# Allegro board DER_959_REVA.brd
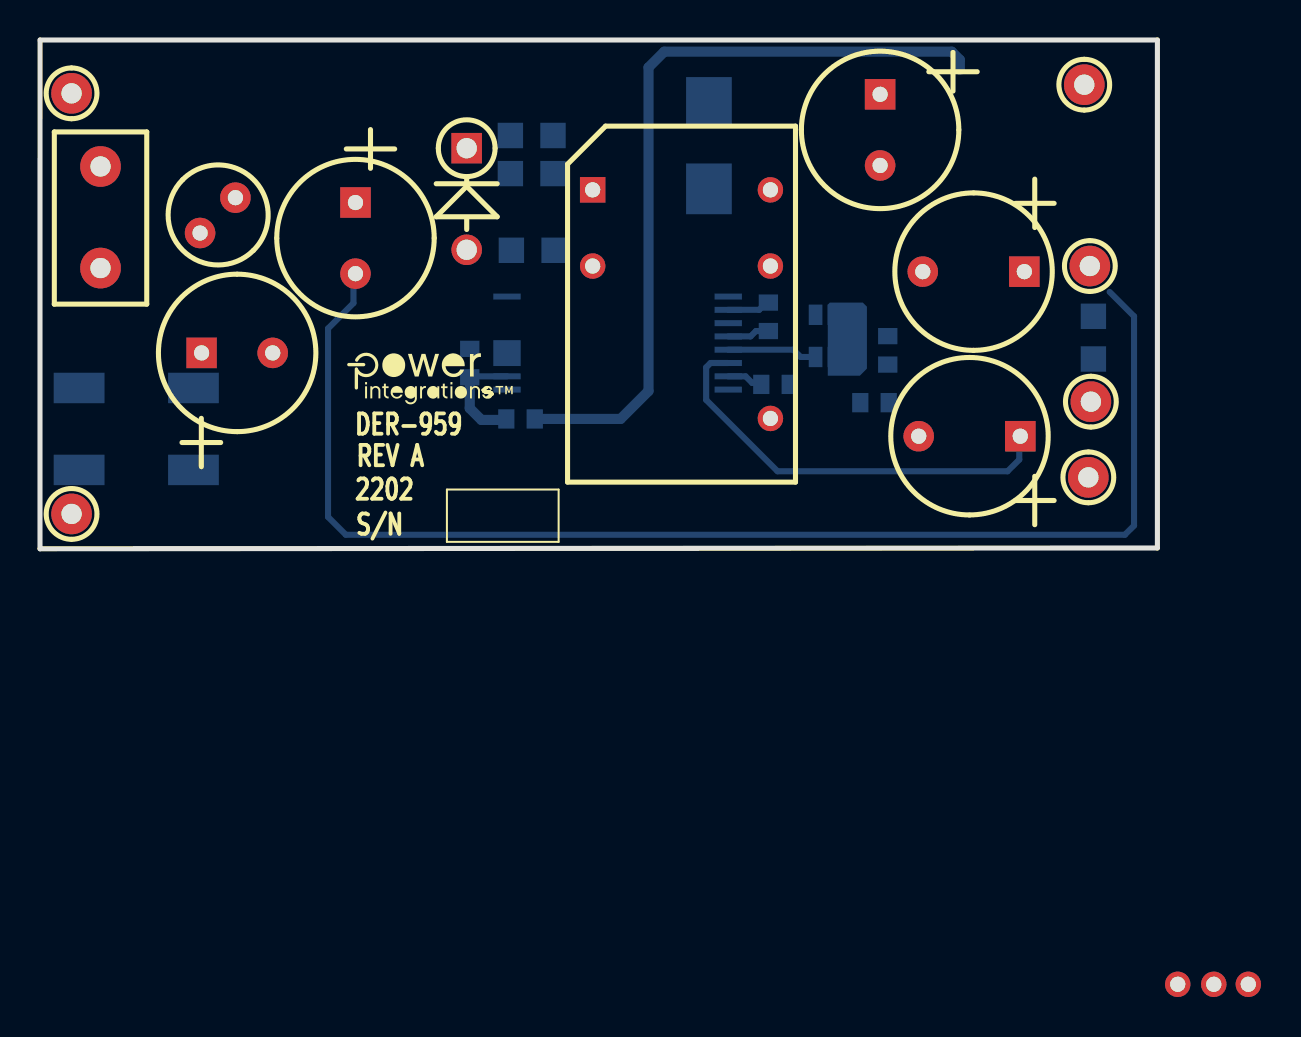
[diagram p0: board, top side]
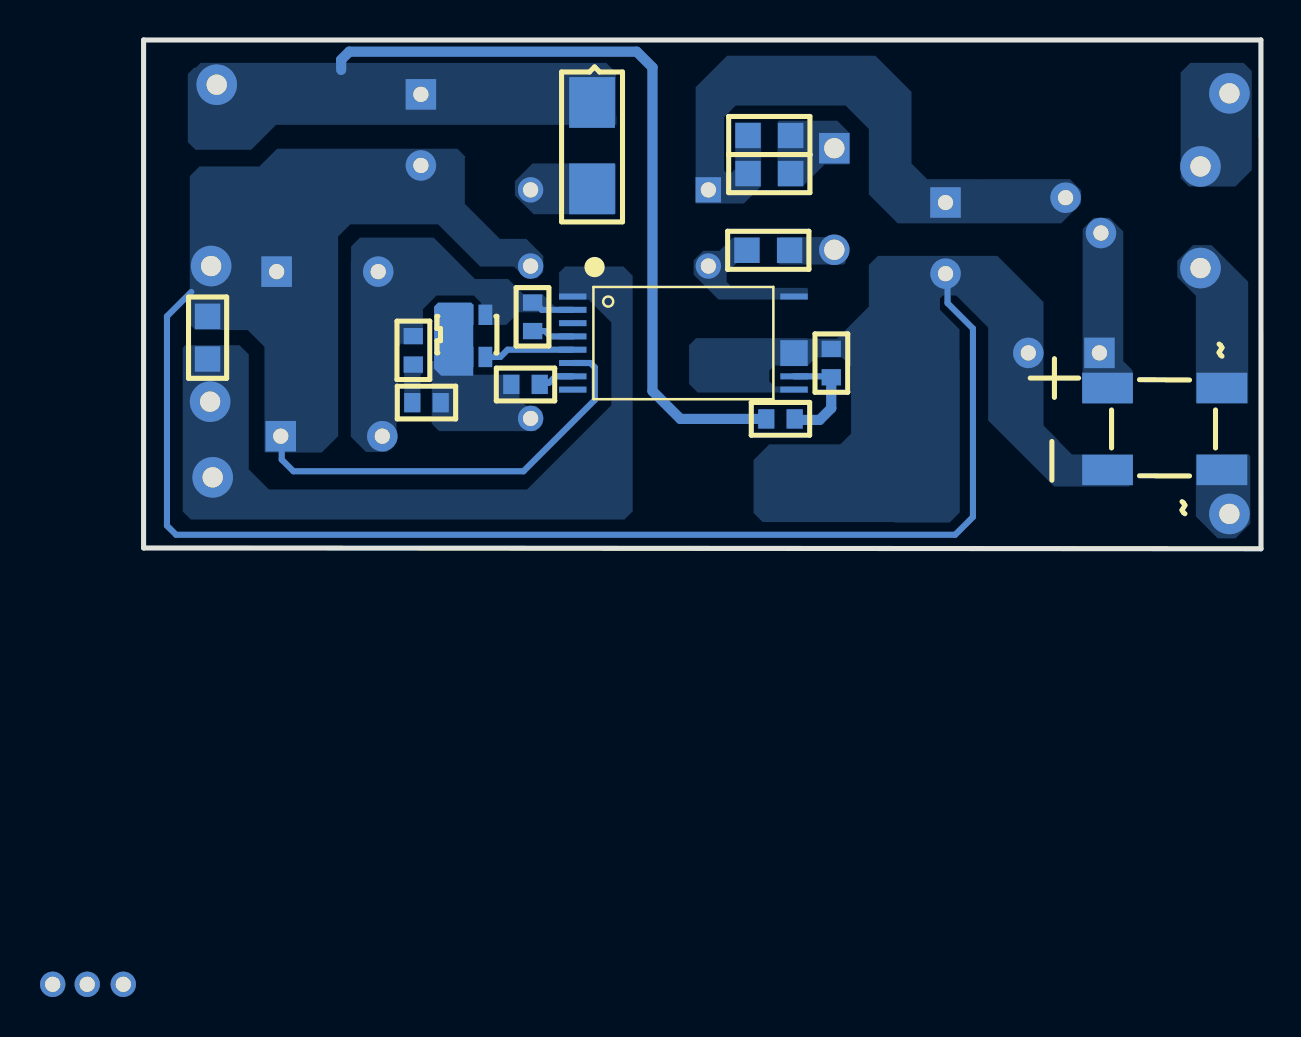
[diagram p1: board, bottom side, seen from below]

Outline 55.89 x 25.44 mm; copper layers: TOP, BOTTOM. Coordinates in mm from the lower left corner of the outline.
Outline path: 0,0 55.89,0.04 55.89,25.44 0.01,25.44 0,0

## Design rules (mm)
constraint set DEFAULT: min track width 0.508

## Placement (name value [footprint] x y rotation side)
BR1  ABS210-13  [PISMD_SOPA-4]  7.68 8.04 90 bottom
C1  4.7 uF  [PIPOLCAPCLYD320LS140030]  8.08 9.79 0 top
C2  4.7 uF  [PIPOLCAPCLYD320LS140030]  15.78 17.31 270 top
C3  220 pF  [PISMC0805]  25.66 18.76 180 bottom
C4  0.47 uF  [PISMC0603]  21.49 8.58 90 bottom
C5  1000 pF  [PISMC0603]  42.4 9.21 90 bottom
C6  2.2 uF  [PISMC0603]  36.43 12.31 270 bottom
C7  1000 uF  [PIPOLCAPCLYD320LS140030]  42.02 22.72 270 top
C8  820 uF  [PI_POLCAP_D320LS200D030]  46.69 13.86 180 top
C9  820 uF  [PI_POLCAP_D320LS200D030]  46.49 5.63 180 top
C10  2.2 uF  [PISMC0805]  52.68 11.62 270 bottom
D1  1N4007  [PIDV200X110X040DO41]  21.34 20.03 270 top
D2  VSSA210-M3/5AT  [PISMDO214AC12]  33.46 22.32 270 bottom
F1  1 A  [PI_RST_MICROFUSE]  3.03 14.04 90 top
L1  330 uH  [PICHOKETOKINVD216H413LS098D030]  8.01 15.79 45 top
LINE  BLK  [PITPKEYSTONE100X100]  1.58 22.77 0 top
NEUTRAL  WHT  [PITPKEYSTONE100X100]  1.58 1.74 0 top
NOREF  -  []  0.01 25.44 0 top
NOREF#2  -  []  0.01 0.04 90 top
NOREF#3  -  []  -140.04 52.4 0 top
NOREF#4  -  []  -217.85 -146.62 0 top
NOREF#5  -  []  14.81 9.69 0 top
Q1  AO6420  [PISMSOT236_SHORT1256]  40.67 9.59 180 bottom
R1  470 k  [PISMR0805]  25.66 20.67 180 bottom
R2  20  [PISMR0805]  23.58 14.93 0 bottom
R3  20  [PISMR0603]  41.03 7.31 0 bottom
R4  47  [PISMR0603]  37.5 8.22 180 bottom
R5  7.5 k  [PISMR0603]  23.32 6.49 0 bottom
T1  EF16  [PIBOBBINEF16V8P]  27.64 17.95 0 top
TP1  YEL  [PITPKEYSTONE100X100]  52.23 23.21 0 top
TP2  RED  [PITPKEYSTONE100X100]  52.51 14.14 0 top
TP3  BLK  [PITPKEYSTONE100X100]  52.56 7.36 0 top
TP4  BLK  [PITPKEYSTONE100X100]  52.43 3.57 0 top
U1  INN3072M  [PI_SM_MINSOP16A_1]  34.42 12.61 270 bottom

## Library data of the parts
BR1 = DIODE BRIDGE_+~~-: alternate symbols: (pismd_SOPA-4a,pi_sm_soic4_slot)
C1 C2 = CAP POL: alternate symbols: (pipolcapclyd320ls140030h)
C3-C5 C10 = CAP NP
C6 = CAP NP: alternate symbols: (pismc0603_1)
C7 = CAP POL: alternate symbols: (pipolcapclyd320ls140d30h750)
C8 C9 = CAP POL
D1 = DIODE: alternate symbols: (pidax475x125040do41,pidv200x110x040do41wbead,pidax390x125040do41)
D2 = DIODE SCHOTTKY
F1 = FUSE: alternate symbols: (pirstmicrofusehoz)
L1 = INDUCTOR
LINE TP1 TP3 TP4 = TESTPOINT: alternate symbols: (TP_TH_CR2_D1_1)
NEUTRAL TP2 = TESTPOINT
Q1 = FET_N_DGS
R1-R3 R5 = R
R4 = R: alternate symbols: (pismr0603_1)
T1 = BEF16/8PINS/GENERIC
U1 = Inno3TNMinSOP16_2

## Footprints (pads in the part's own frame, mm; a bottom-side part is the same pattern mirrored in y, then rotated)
PI_POLCAP_D320LS200D030
  rect 1.524x1.524 hole 0.762: 1(-2.54,0)
  round 1.524 hole 0.762: 2(2.54,0)
PI_RST_MICROFUSE
  round 2.032 hole 1.016: 1(0,0) 2(5.08,0)
PI_SM_MINSOP16A_1
  rect 0.3x1.369 smd: 1(0,0) 2(0.665,0) 3(1.331,0) 4(1.994,0) 5(2.659,0) 6(3.325,0) 7(3.99,0) 8(4.656,0) 9(4.656,11.067) 10(3.99,11.067) 16(0,11.067)
  rect 1.293x1.369 smd: 11(2.83,11.067)
PIBOBBINEF16V8P
  rect 1.27x1.27 hole 0.762: 1(0,0)
  round 1.27 hole 0.762: 2(0,-3.81) 3(29.261,-39.726) 4(31.064,-39.726) 5(8.89,-11.43) 6(32.791,-39.726) 7(8.89,-3.81) 8(8.89,0)
PICHOKETOKINVD216H413LS098D030
  round 1.524 hole 0.762: 1(0,0) 2(2.499,0)
PIDV200X110X040DO41
  rect 1.524x1.524 hole 1.016: 1(0,0)
  round 1.524 hole 1.016: 2(5.08,0)
PIPOLCAPCLYD320LS140030
  rect 1.524x1.524 hole 0.762: 1(0,0)
  round 1.524 hole 0.762: 2(3.556,0)
PISMC0603
  rect 0.813x0.965 smd: 1(0,0) 2(1.422,0)
PISMC0805
  rect 1.27x1.27 smd: 1(0,0) 2(2.134,0)
PISMD_SOPA-4
  rect 1.524x2.54 smd: 1(0,0) 2(0,-5.72) 3(-4.1,-5.72) 4(-4.1,0)
PISMDO214AC12
  rect 2.54x2.286 smd: 1(0,0) 2(4.318,0)
PISMR0603
  rect 0.813x0.965 smd: 1(0,0) 2(1.422,0)
PISMR0805
  rect 1.27x1.27 smd: 1(0,0) 2(2.134,0)
PISMSOT236_SHORT1256
  rect 0.686x1.016 smd: (0,2.108) (0.94,0) (0.94,2.108) 1(0,0) 3(1.88,0) 4(1.88,2.108)
PITPKEYSTONE100X100
  round 2.032 hole 1.016: 1(0,0)

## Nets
+12V: C7.1 D2.1 R5.2 TP1.1
3: U1.3
8: U1.8
RTN: C10.2 TP3.1 TP4.1 U1.1
N12175216: F1.2 LINE.1
N12175256: BR1.1 C1.1 L1.1
N12175292: C2.1 C3.1 L1.2 R1.1 T1.1
N12175504: C3.2 D1.1 R1.2
N12175524: BR1.4 C1.2 C2.2 C4.2 C7.2 C8.1 C9.1 C10.1 T1.7 TP2.1 U1.6 U1.9 U1.11
N12175646: Q1.1 R3.1 R4.1 T1.5
N12175650: C5.1 R3.2
N12175654: C5.2 C6.1 C8.2 C9.2 Q1.4(S) U1.2
N12175712: D1.2 R2.1
N12175716: R2.2 T1.2 U1.16
N12175890: Q1.3 U1.5
N12175950: BR1.3 NEUTRAL.1
N12175954: C6.2 U1.4
N12176066: C4.1 R5.1 U1.10
N12179234: R4.2 U1.7
N12183686: D2.2 T1.8
N12199280: BR1.2 F1.1

Pads without a net: T1 3 4 6

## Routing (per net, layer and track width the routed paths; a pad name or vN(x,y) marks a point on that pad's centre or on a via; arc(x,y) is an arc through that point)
+12V: length 39
  BOTTOM w0.508: 46,23.94 46,24.45 45.6,24.86 31.22,24.86 30.43,24.07 30.43,7.89 29.04,6.49 R5.2
N12175524: length 87.2
  BOTTOM w0.305: C9.1 48.98,5.58 48.98,4.46 48.39,3.88 36.89,3.88 33.32,7.44 33.32,9.07 33.54,9.29 U1.6 ; 53.5,12.84 54.72,11.62 54.72,1.16 54.26,0.7 15.3,0.7 14.41,1.59 14.41,11.01 15.68,12.28 15.68,13.27 15.83,13.43 15.83,13.71 C2.2
N12175654: length 2.2
  BOTTOM w0.305: U1.2 35.97,11.95 36.33,12.31 C6.1
N12175716: length 0.2
  BOTTOM w0.508: 27.61,14.21 27.79,14.21
N12175890: length 4.5
  BOTTOM w0.305: Q1.3 38.04,9.59 37.68,9.95 U1.5
N12175954: length 2.1
  BOTTOM w0.305: U1.4 35.54,10.62 35.81,10.89 C6.2
N12176066: length 5.5
  BOTTOM w0.305: U1.10 21.54,8.62 C4.1
  BOTTOM w0.508: R5.1 23.27,6.44 22.08,6.44 21.49,7.03 C4.1
N12179234: length 1.8
  BOTTOM w0.305: U1.7 35.29,8.62 35.62,8.3 36,8.3 R4.2

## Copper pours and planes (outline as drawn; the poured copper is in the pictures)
+12V on BOTTOM: 32.26,23.82 32.26,21.68 32.24,21.66 32.24,21.17 32.26,21.2 49.26,21.2 50.5,19.95 53.29,19.95 53.68,20.34 53.68,23.74 53.36,24.06 53.27,24.06 53.03,24.3 32.75,24.3
RTN on BOTTOM: 53.8,10.18 53.93,10.05 53.93,1.87 53.52,1.46 31.83,1.46 31.42,1.87 31.42,13.66 31.88,14.11 34.8,14.11 35.11,13.81 35.11,12.56 35.01,12.46 33.63,12.46 32.49,11.32 32.49,7.18 36.71,2.96 49.61,2.96 50.63,3.98 50.63,9.72 51.08,10.18
N12175216 on BOTTOM: 1.29,18.11 0.46,18.94 0.46,23.89 0.87,24.3 3.54,24.3 4.02,23.82 4.02,18.53 3.6,18.11
N12175256 on BOTTOM: 8.92,15.99 8.92,7.25 8.91,7.24 6.43,7.24 6.43,8.93 6.89,9.39 6.89,15.86 7.57,16.55 8.36,16.55
N12175292 on BOTTOM: 19.26,24.65 26.7,24.65 28.28,23.08 28.28,17.26 25.86,17.26 25,18.13 25,21.3 26.29,21.3 26.29,18.99 26.5,18.79 26.73,18.79 26.85,18.91 26.85,21.58 26.27,22.16 20.78,22.16 19.61,21 19.61,17.72 18.17,16.27 9.99,16.27 9,17.26 9,17.92 9.56,18.48 14.13,18.48 14.15,18.46 14.18,18.48 16.69,18.48 17.48,19.27 17.48,22.85 19.26,24.63
N12175504 on BOTTOM: 24.11,21.4 24.19,21.33 24.19,18.15 24.16,18.13 22.92,18.13 21.82,19.22 20.6,19.22 20.58,19.24 20.58,20.79 21.19,21.4
N12175524 on BOTTOM: 40.19,20.01 49.2,20.01 50.09,19.12 53.09,19.12 53.57,18.63 53.57,11.22 53.29,10.94 50.68,10.94 49.84,10.1 49.84,4.84 49.81,4.82 46.97,4.82 46.16,5.63 46.16,15.61 45.55,16.22 41.15,16.22 39.04,14.11 37.37,14.11 36.78,13.53 36.2,13.53 35.9,13.83 35.9,14.65 36.75,15.5 38.07,15.5 39.82,17.25 39.82,19.56 39.78,19.6
N12175524 on BOTTOM: 13.19,14.65 19.16,14.65 19.61,14.19 19.61,12.11 21.21,10.51 22.69,10.51 22.71,10.53 28.25,10.53 28.61,10.18 28.61,8.24 28.17,7.81 22.66,7.81 22.66,8.09 22.69,8.12 24.34,8.12 24.59,8.37 24.59,8.91 24.34,9.16 22.66,9.16 22.26,9.57 20.96,9.57 20.5,9.11 20.5,5.76 21.04,5.22 24.59,5.22 25.38,4.43 25.38,1.79 24.92,1.34 18.34,1.34 18.32,1.31 15.58,1.31 15.07,1.82 15.07,9.44 15.08,9.45 15.08,10.98 16.06,11.95 16.06,12.51 15.91,12.66 15.25,12.66 13.64,11.06 13.64,6.42 10.34,3.11 6.61,3.11 6.43,3.29 6.43,4.69 6.46,4.71 9.45,4.71 10.1,5.36 10.1,5.39 10.88,6.16 10.88,12.33
N12175646 on BOTTOM (solid shape): 41.36,12.11 41.36,9.01 41,8.65 39.4,8.65 39.4,12.21 39.5,12.31 41.15,12.31
N12175646 on BOTTOM: 35.95,6.21 35.95,6.85 36.25,7.15 36.76,7.15 37.09,7.48 37.09,8.7 39.4,8.7 39.5,8.8 39.5,9.39 41.46,9.39 41.46,8.73 41.47,8.71 41.47,6.25 41.1,5.88 36.28,5.88
N12175650 on BOTTOM: 41.92,9.46 42.04,9.59 42.8,9.59 42.85,9.54 42.85,6.9 42.8,6.85 42.12,6.85 42.04,6.92 42.04,8.68 41.92,8.8
N12175654 on BOTTOM: 45.52,5.6 45.52,14.37 45.51,14.38 45.51,15.12 45.06,15.56 41.38,15.56 39.31,13.49 37.65,13.49 36.9,12.74 35.95,12.74 35.29,12.08 35.29,11.83 37.11,11.83 37.75,11.19 39.02,11.19 39.02,12.31 39.38,12.66 41.23,12.66 41.92,11.98 41.92,10.38 42.04,10.25 43.01,10.25 43.24,10.02 43.24,5.3 43.26,5.3 43.72,4.84 44.76,4.84
N12175712 on BOTTOM: 24.03,15.59 21.01,15.59 20.78,15.36 20.78,14.29 20.86,14.21 24.08,14.21 24.16,14.29 24.16,15.46
N12175716 on BOTTOM: 25.07,15.56 26.42,15.56 27.08,14.9 27.89,14.9 28.38,14.42 28.38,13.71 27.13,12.46 22.66,12.46 22.66,12.99 22.71,13.05 26.17,13.05 26.18,13.06 26.43,13.06 26.73,13.35 26.73,13.78 26.22,14.29 25.1,14.29 25.07,14.32
N12175950 on BOTTOM: 2.16,0.52 1.28,0.52 0.54,1.26 0.54,4.64 0.64,4.74 3.21,4.74 3.26,4.69 3.26,1.62
N12183686 on BOTTOM: 37.32,18.38 37.32,17.67 36.38,16.73 32.31,16.73 32.26,16.78 32.26,19.22 32.31,19.27 36.43,19.27
N12199280 on BOTTOM: 4.18,14.4 4.18,13.58 3.26,12.65 3.26,7.31 3.21,7.25 0.67,7.25 0.64,7.28 0.64,13.35 2.47,15.18 3.41,15.18

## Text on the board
Ref Des/Silkscreen Top: DER-959 | 2202 | S/N | REV A
FAB_NOTES: 13   MATERIAL FR4 COPPER 2oz THICKNESS 0.062" | PLEASE DELETE THESE PINS
User.7: FIGURE | FINISHED_SIZE | 30.0 | 40.0 | DRILL CHART: TOP to BOTTOM | ALL UNITS ARE IN MILS | TOLERANCE_DRILL | +0.0/-0.0 | +3.0/-3.0 | PLATED | QTY | 10 | 2 | 6
